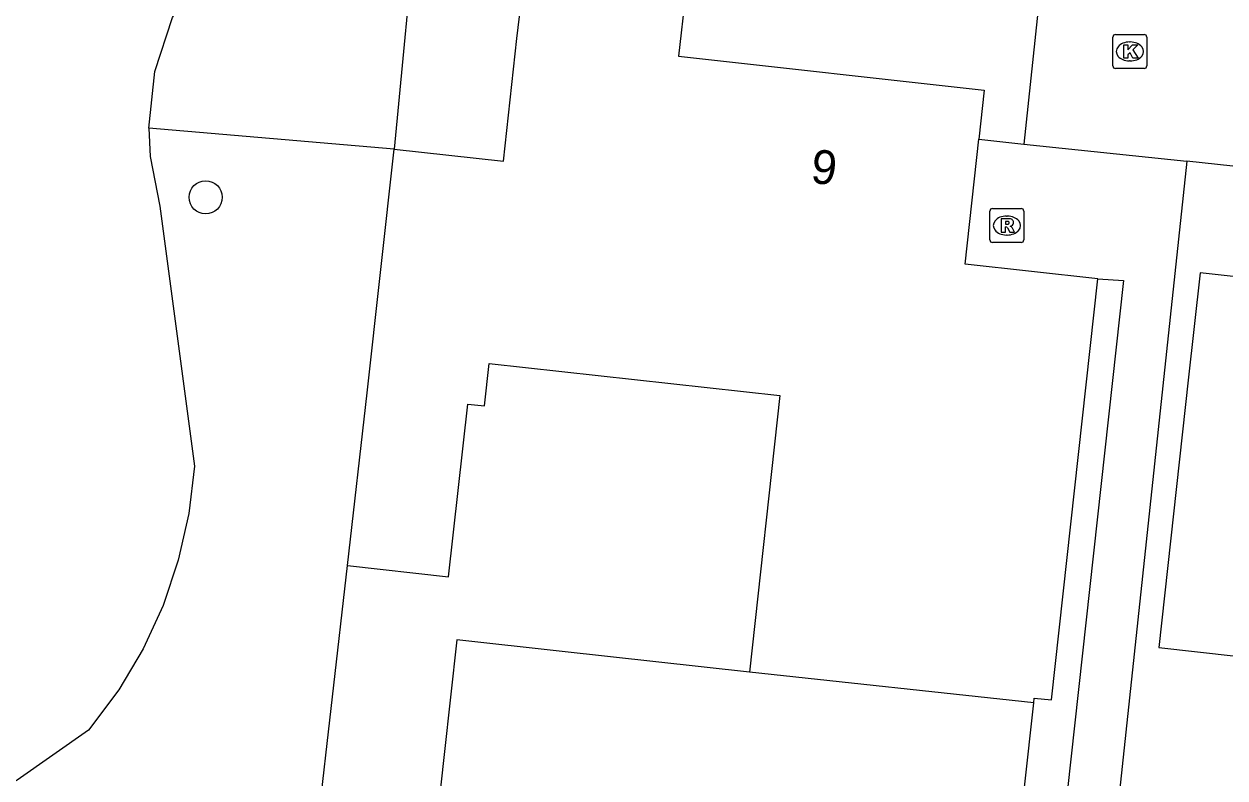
# Model space of a CAD drawing. Extents: x 162398 to 163643, y 386453 to 387397.
# Drawn here: x 162580.44 to 162615.85, y 386645.28 to 386667.51 of the extents above; entities that cross this region are included whole.
import ezdxf

# ---------------------------------------------------------------- set-up
doc = ezdxf.new("R2010")
doc.units = 0
for name, color, linetype in [('IMGEO_Boom', 7, 'Continuous'), ('IMGEO_Groenvoorziening', 7, 'Continuous'), ('IMGEO_Kolk', 7, 'Continuous'), ('IMGEO_Pand', 7, 'Continuous'), ('IMGEO_Pand_nummerreeks', 7, 'Continuous'), ('IMGEO_Rijbaan_lokaal_open', 7, 'Continuous'), ('IMGEO_Rioolput', 7, 'Continuous'), ('IMGEO_Voetpad_open', 7, 'Continuous')]:
    doc.layers.add(name, color=color, linetype=linetype)

msp = doc.modelspace()

# ---------------------------------------------------------------- linework, layer by layer
at = {"layer": 'IMGEO_Boom'}
msp.add_circle((162585.797, 386662.4), 0.489, dxfattribs=at)
at = {"layer": 'IMGEO_Groenvoorziening'}
for points in [[(162584.117, 386664.44), (162584.297, 386666.11), (162584.82, 386667.705), (162585.664, 386669.157), (162587.003, 386670.859), (162588.62, 386672.535), (162590.404, 386674.032), (162590.907, 386674.421), (162591.332, 386674.478), (162591.645, 386674.404), (162591.999, 386674.162), (162592.182, 386673.897), (162592.283, 386673.481), (162592.242, 386673.162), (162592.028, 386670.923)], [(162592.028, 386670.923), (162591.351, 386663.817)], [(162584.117, 386664.44), (162584.159, 386663.601), (162584.448, 386662.137), (162585.464, 386654.475), (162585.3, 386653.076), (162584.991, 386651.702), (162584.54, 386650.368), (162583.952, 386649.088), (162583.233, 386647.877), (162582.341, 386646.687), (162580.239, 386645.21), (162577.994, 386643.962), (162575.154, 386642.786), (162571.863, 386642.938), (162568.605, 386643.432), (162565.417, 386644.265), (162562.706, 386645.266), (162557.329, 386647.367), (162555.62, 386647.57), (162554.758, 386647.536), (162553.905, 386647.412), (162552.759, 386647.097)], [(162591.351, 386663.817), (162584.117, 386664.44)], [(162587.764, 386632.176), (162589.976, 386651.544)]]:
    msp.add_lwpolyline(points, dxfattribs=at)
at = {"layer": 'IMGEO_Kolk'}
for p, q in [((162612.543, 386666.274), (162612.543, 386667.126)), ((162612.618, 386667.2), (162613.47, 386667.2)), ((162613.031, 386666.98), (162613.056, 386666.98)), ((162613.544, 386667.126), (162613.544, 386666.274)), ((162613.054, 386666.42), (162613.029, 386666.42)), ((162613.47, 386666.2), (162612.618, 386666.2))]:
    msp.add_line(p, q, dxfattribs=at)
for points in [[(162612.543, 386666.274), (162612.543, 386667.126)], [(162612.618, 386667.2), (162613.47, 386667.2)], [(162613.544, 386667.126), (162613.544, 386666.274)], [(162612.864, 386666.9), (162612.987, 386666.9), (162612.987, 386666.749), (162613.117, 386666.9), (162613.281, 386666.9), (162613.135, 386666.749), (162613.288, 386666.5), (162613.136, 386666.5), (162613.051, 386666.664), (162612.987, 386666.597), (162612.987, 386666.5), (162612.864, 386666.5), (162612.864, 386666.9)], [(162613.47, 386666.2), (162612.618, 386666.2)]]:
    msp.add_lwpolyline(points, dxfattribs=at)
for centre, start, end in [((162612.62, 386667.124), 91.552, 178.448), ((162612.62, 386667.124), 91.552, 178.448), ((162613.468, 386667.124), 1.552, 88.448), ((162613.468, 386667.124), 1.552, 88.448), ((162612.62, 386666.276), 181.552, 268.448), ((162612.62, 386666.276), 181.552, 268.448), ((162613.468, 386666.276), 271.552, 358.448), ((162613.468, 386666.276), 271.552, 358.448)]:
    msp.add_arc(centre, 0.0765, start, end, dxfattribs=at)
for centre, major_axis, ratio, start_param, end_param in [((162613.03, 386666.7), (-0.387, 0.002), 0.722429, 4.712389, 7.853982), ((162613.055, 386666.7), (-0.39, 0.002), 0.717154, 1.570796, 4.712389)]:
    msp.add_ellipse(centre, major_axis=major_axis, ratio=ratio, start_param=start_param, end_param=end_param, dxfattribs=at)
at = {"layer": 'IMGEO_Pand'}
for points in [[(162591.351, 386663.817), (162594.573, 386663.463), (162594.971, 386667.081), (162595.168, 386668.713), (162599.619, 386668.21), (162599.642, 386668.409), (162599.94, 386668.376), (162599.735, 386666.557), (162608.75, 386665.564), (162608.59, 386664.114)], [(162589.976, 386651.544), (162590.56, 386656.632), (162591.351, 386663.817)], [(162612.099, 386659.995), (162608.185, 386660.426), (162608.59, 386664.114)], [(162630.059, 386640.442), (162630.508, 386640.393), (162631.867, 386652.737), (162631.302, 386652.8), (162631.91, 386658.314), (162623.144, 386659.279), (162623.397, 386661.568), (162618.457, 386662.113), (162618.205, 386659.827), (162615.115, 386660.168), (162614.767, 386657.009), (162613.898, 386649.122), (162617.313, 386648.746), (162617.912, 386654.19), (162626.551, 386653.238), (162625.201, 386640.975)], [(162610.208, 386647.493), (162610.224, 386647.635), (162610.731, 386647.58), (162612.099, 386659.995)], [(162589.976, 386651.544), (162592.958, 386651.21), (162593.528, 386656.305), (162594.014, 386656.252), (162594.151, 386657.498), (162602.729, 386656.552), (162601.831, 386648.402)], [(162601.831, 386648.402), (162596.304, 386649.01), (162593.2, 386649.351), (162592.828, 386645.969), (162592.041, 386638.819), (162595.395, 386638.449), (162595.981, 386643.772), (162604.668, 386642.815), (162603.325, 386630.619), (162608.688, 386630.029), (162610.068, 386642.562), (162609.67, 386642.605), (162610.208, 386647.493)], [(162610.208, 386647.493), (162601.831, 386648.402)]]:
    msp.add_lwpolyline(points, dxfattribs=at)
at = {"layer": 'IMGEO_Rijbaan_lokaal_open'}
for points in [[(162609.749, 386669.065), (162610.449, 386668.978), (162609.92, 386663.966)], [(162609.92, 386663.966), (162614.719, 386663.466)], [(162628.73, 386617.707), (162633.187, 386658.247), (162633.536, 386661.425), (162614.719, 386663.466)]]:
    msp.add_lwpolyline(points, dxfattribs=at)
at = {"layer": 'IMGEO_Rioolput'}
for p, q in [((162608.992, 386662.068), (162609.844, 386662.068)), ((162608.917, 386661.142), (162608.917, 386661.994)), ((162609.405, 386661.848), (162609.43, 386661.848)), ((162609.918, 386661.994), (162609.918, 386661.142)), ((162609.844, 386661.068), (162608.992, 386661.068)), ((162609.428, 386661.288), (162609.403, 386661.288))]:
    msp.add_line(p, q, dxfattribs=at)
for points in [[(162608.992, 386662.068), (162609.844, 386662.068)], [(162608.917, 386661.142), (162608.917, 386661.994)], [(162609.506, 386661.766), (162609.254, 386661.768), (162609.254, 386661.368)], [(162609.432, 386661.687), (162609.378, 386661.687), (162609.378, 386661.606)], [(162609.918, 386661.994), (162609.918, 386661.142)], [(162609.254, 386661.368), (162609.378, 386661.368), (162609.378, 386661.53), (162609.389, 386661.53)], [(162609.378, 386661.606), (162609.43, 386661.606)], [(162609.436, 386661.501), (162609.507, 386661.368), (162609.647, 386661.368), (162609.582, 386661.494)], [(162609.844, 386661.068), (162608.992, 386661.068)]]:
    msp.add_lwpolyline(points, dxfattribs=at)
for centre, radius, start, end in [((162608.994, 386661.992), 0.0765, 91.552, 178.448), ((162608.994, 386661.992), 0.0765, 91.552, 178.448), ((162609.842, 386661.992), 0.0765, 1.552, 88.448), ((162609.842, 386661.992), 0.0765, 1.552, 88.448), ((162609.438, 386661.591), 0.0964, 77.0061, 93.1865), ((162609.452, 386661.648), 0.0378, 276.6634, 79.6772), ((162609.505, 386661.656), 0.109, 350.3612, 89.416), ((162609.388, 386661.477), 0.0533, 26.0293, 88.6989), ((162609.414, 386661.795), 0.19, 274.7715, 282.9687), ((162609.503, 386661.656), 0.112, 277.5842, 350.9817), ((162609.487, 386661.441), 0.108, 29.5134, 73.7905), ((162608.994, 386661.144), 0.0765, 181.552, 268.448), ((162608.994, 386661.144), 0.0765, 181.552, 268.448), ((162609.842, 386661.144), 0.0765, 271.552, 358.448), ((162609.842, 386661.144), 0.0765, 271.552, 358.448)]:
    msp.add_arc(centre, radius, start, end, dxfattribs=at)
for centre, major_axis, ratio, start_param, end_param in [((162609.404, 386661.568), (-0.387, 0.002), 0.722429, 4.712389, 7.853982), ((162609.429, 386661.568), (-0.39, 0.002), 0.717154, 1.570796, 4.712389)]:
    msp.add_ellipse(centre, major_axis=major_axis, ratio=ratio, start_param=start_param, end_param=end_param, dxfattribs=at)
at = {"layer": 'IMGEO_Voetpad_open'}
for points in [[(162608.59, 386664.114), (162609.92, 386663.966)], [(162614.719, 386663.466), (162610.524, 386624.181)], [(162612.099, 386659.995), (162612.855, 386659.948), (162608.983, 386624.745)]]:
    msp.add_lwpolyline(points, dxfattribs=at)

# ---------------------------------------------------------------- texts
at = {"layer": 'IMGEO_Pand_nummerreeks'}
msp.add_text('9', height=1, rotation=353.7142, dxfattribs=at).set_placement((162603.609, 386662.831))

doc.saveas('drawing.dxf')
